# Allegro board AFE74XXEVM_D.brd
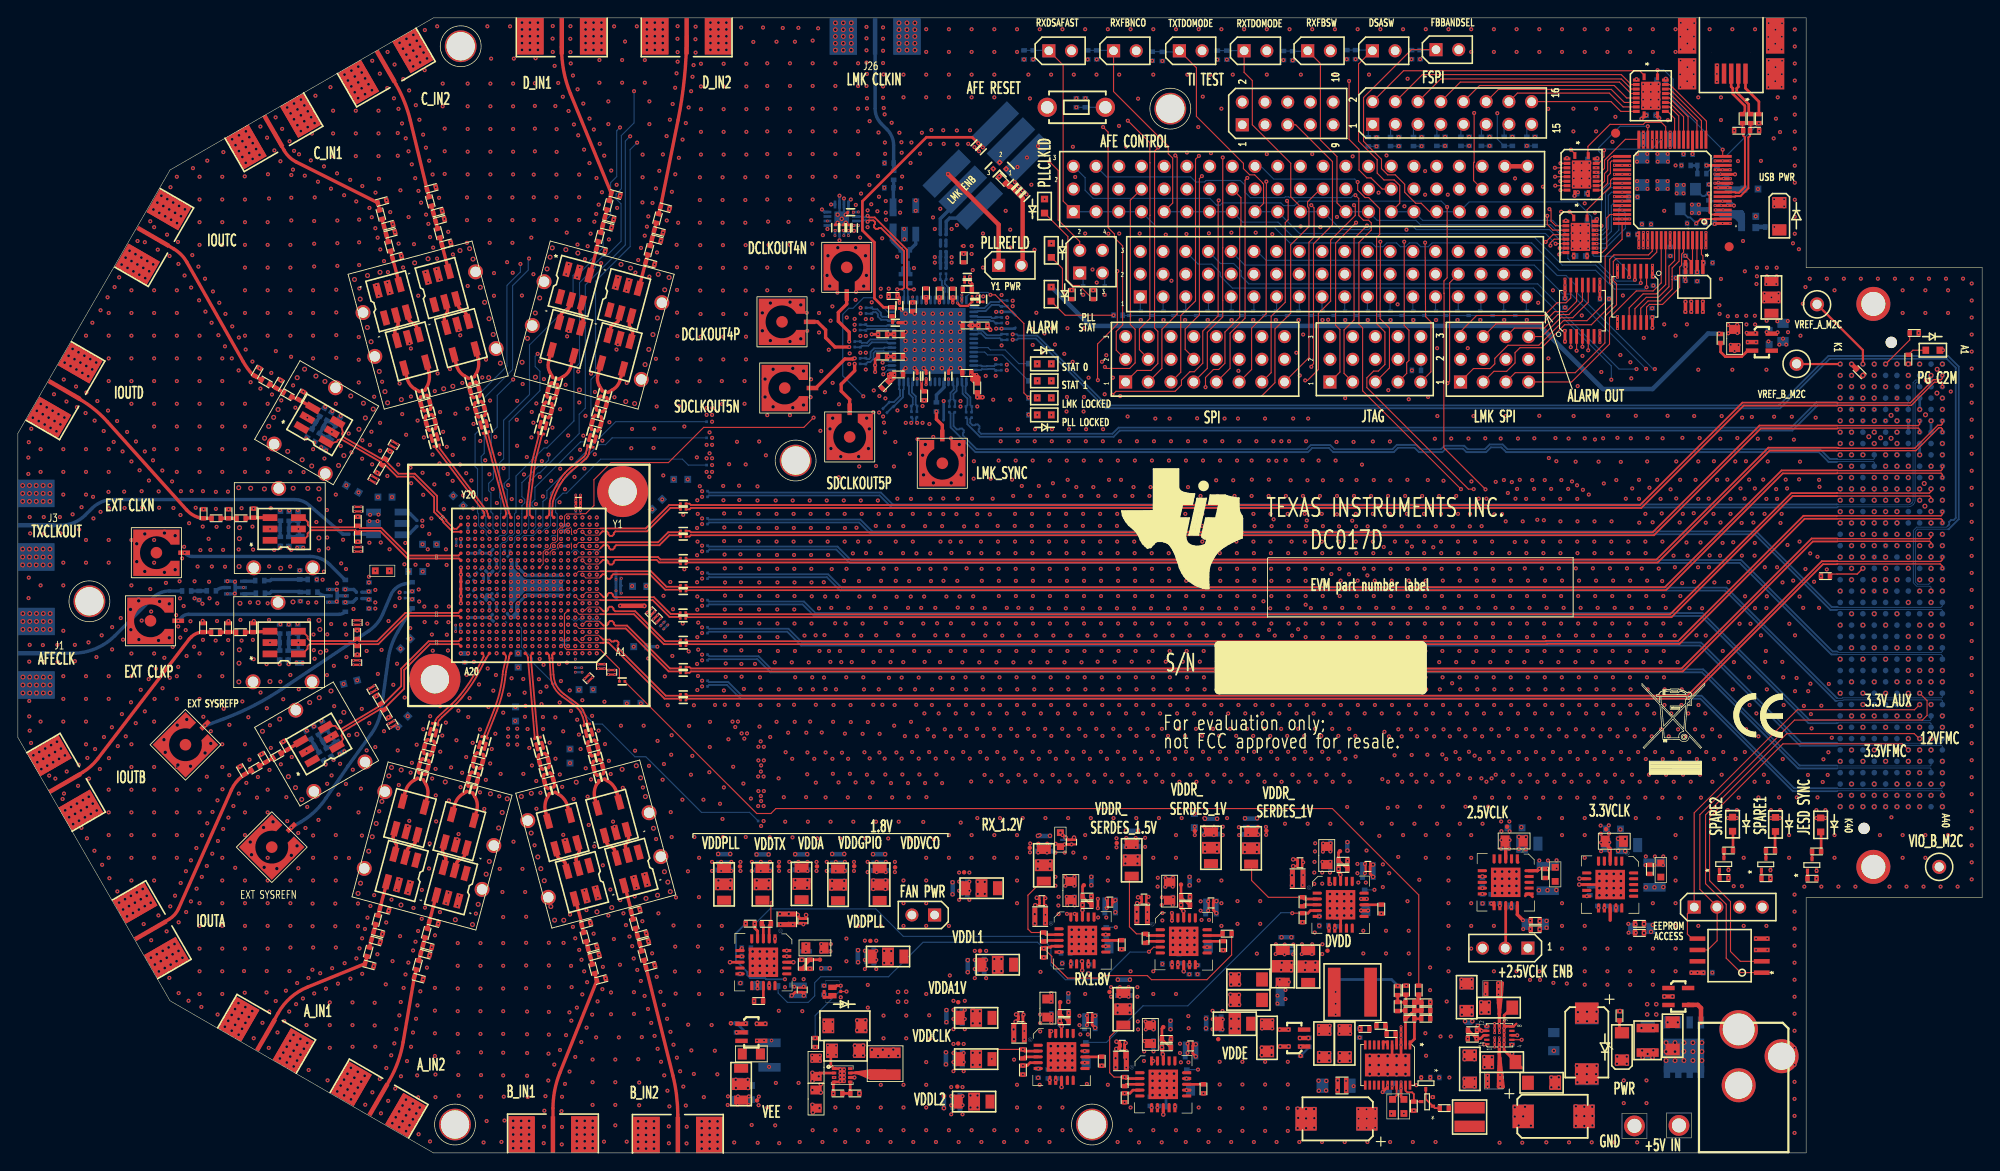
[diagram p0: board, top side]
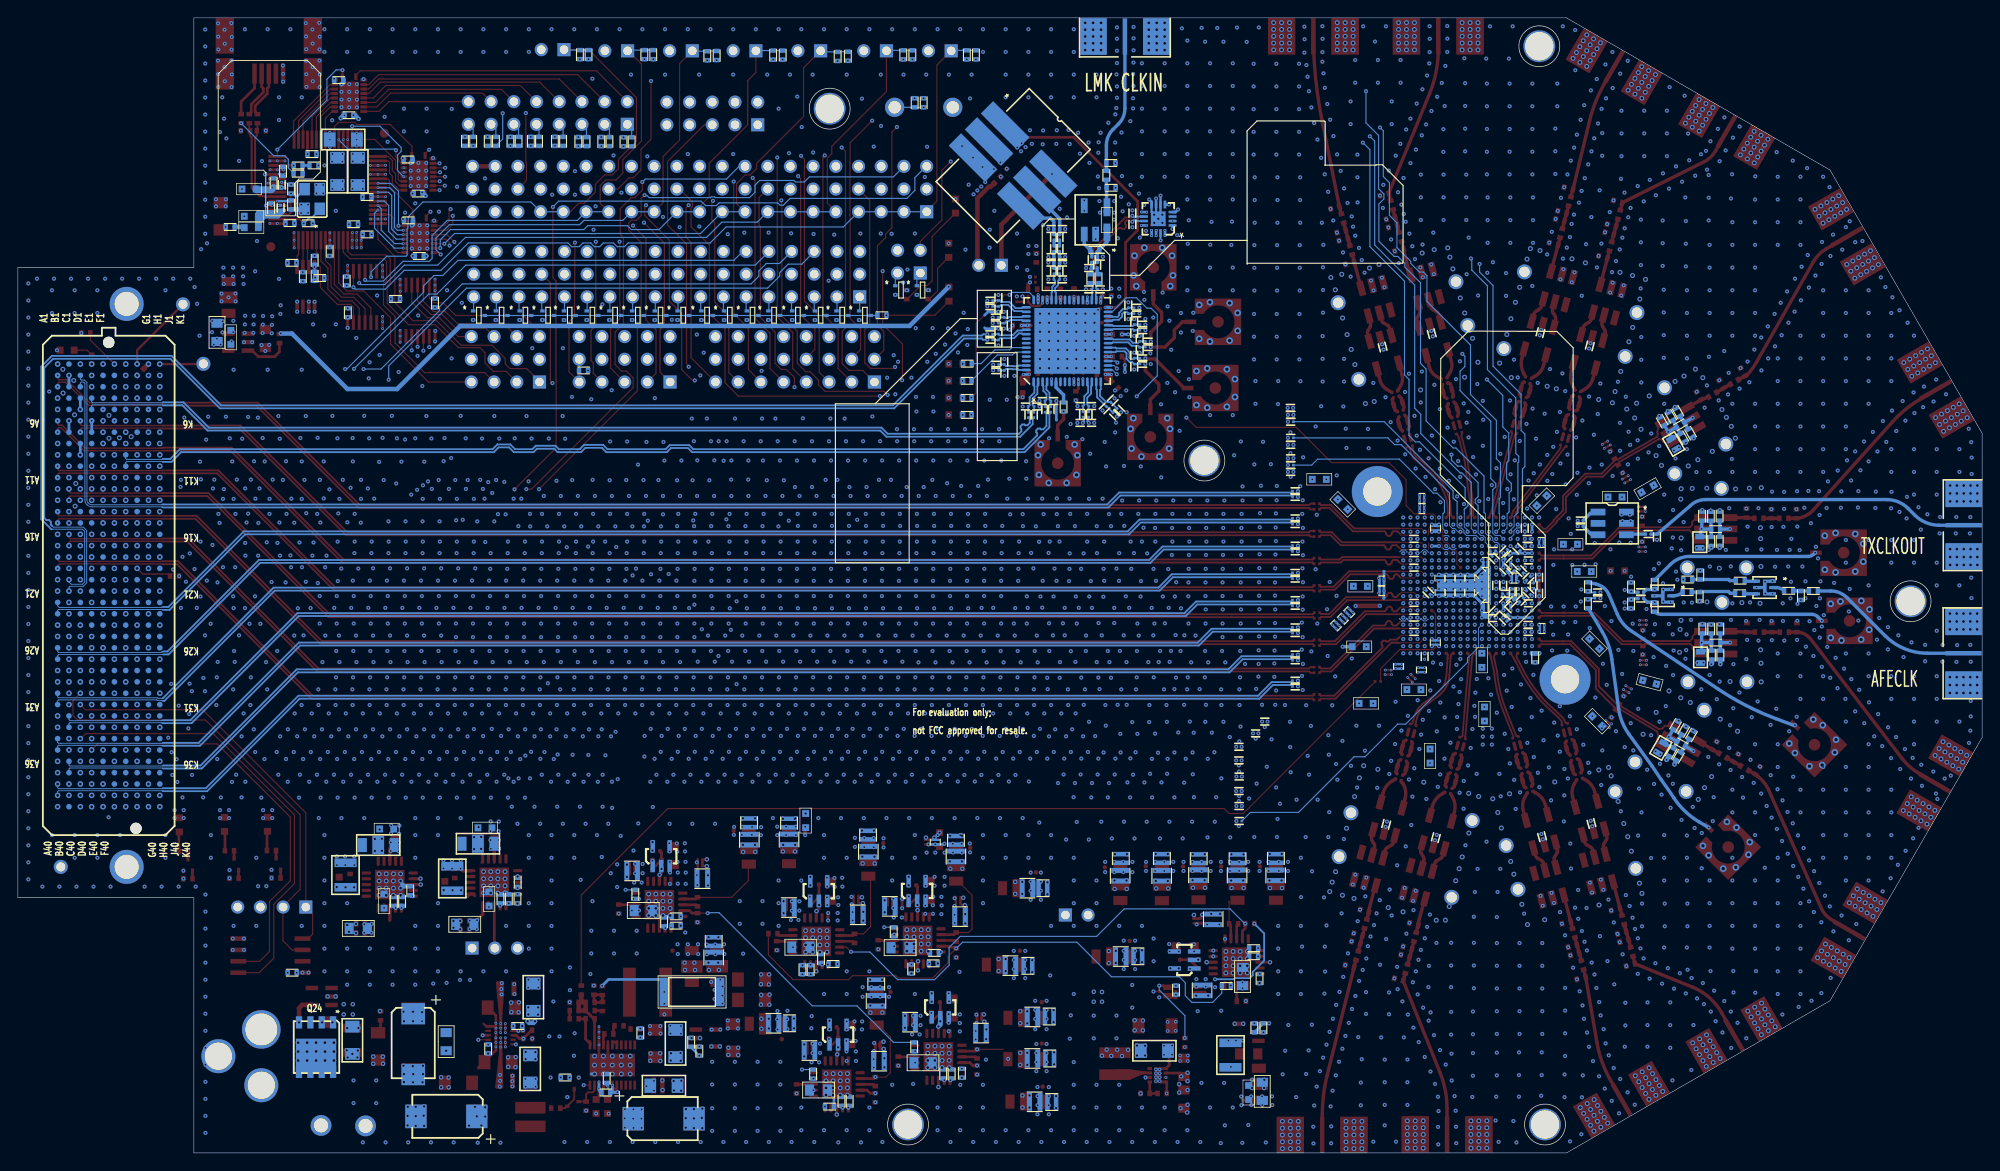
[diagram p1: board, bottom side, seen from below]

Outline 219.71 x 127 mm; copper layers: TOP, L2_GND, L3_PWR, L4_SIG, L5_GND, L6_SIG, L7_GND, L8_PWR_SIG, L9_GND, BOTTOM. Coordinates in mm from the lower left corner of the outline.
Outline path: 0,80.52 0,46.48 17.02,17.02 46.48,0 200.03,0 200.03,28.57 219.71,28.57 219.71,99.06 200.03,99.06 200.03,127 46.48,127 17.02,109.98 0,80.52

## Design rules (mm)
net group ADC_ALT_SYNC: nets ADC_ALT_SYNC_N ADC_ALT_SYNC_P
net group ADC_SYNC: nets ADC_SYNC_N ADC_SYNC_P
net group AIN1: nets AIN1M AIN1P
net group AIN2: nets AIN2M AIN2P
net group BIN1: nets BIN1M BIN1P
net group BIN2: nets BIN2M BIN2P
net group CAR_SYSREF: nets CAR_SYSREFM CAR_SYSREFP
net group CARSYSREF: nets CAR_SYSREF_M CAR_SYSREF_P
net group CIN1: nets CIN1M CIN1P
net group CIN2: nets CIN2M CIN2P
net group CLK: nets CLKN CLKP
net group CLK0_M2C: nets CLK0_M2C_N CLK0_M2C_P
net group CLK1_M2C: nets CLK1_M2C_N CLK1_M2C_P
net group CLK_LAO: nets CLK_LAO_0M CLK_LAO_0P
net group CLKIN1: nets CLKIN1_N CLKIN1_P
net group DAC_ALT_SYNC: nets DAC_ALT_SYNC_N DAC_ALT_SYNC_P
net group DAC_SYNC: nets DAC_SYNC_N DAC_SYNC_P
net group DCLKOUT4: nets DCLKOUT4N DCLKOUT4P
net group DCLKOUT6: nets DCLKOUT6N DCLKOUT6P
net group DCLKOUT10: nets DCLKOUT10N DCLKOUT10P
net group DIN1: nets DIN1M DIN1P
net group DIN2: nets DIN2M DIN2P
net group DP0_M2C: nets DP0_M2C_N DP0_M2C_P
net group DP1: nets DM DP
net group DP1_M2C: nets DP1_M2C_N DP1_M2C_P
net group DP2: nets CLKLA_0M CLKLA_0P
net group DP3: nets N19392142 N19392187
net group DP4: nets CLK_N CLK_P
net group DP5: nets FPGA_CLK1N FPGA_CLK1P
net group DP6: nets FPGA_CLK2N FPGA_CLK2P
net group DP7: nets OSCI OSCO
net group DP8: nets N19086842 N19086844
net group DP9: nets GTXCLKM GTXCLKP
net group DP10: nets GTX_CLKM GTX_CLKP
net group DP11: nets N18276385 N18284119
net group FPGA_CLK1: nets FPGA_CLK1_N FPGA_CLK1_P
net group FPGA_CLK2: nets FPGA_CLK2_N FPGA_CLK2_P
net group GBTCLK1_M2C: nets GBTCLK1_M2C_N GBTCLK1_M2C_P
net group LMK_CLKIN1: nets CLKIN1N CLKIN1P
net group OSCIN: nets OSCINN OSCINP
net group RX1: nets RX1N RX1P
net group RX2: nets RX2N RX2P
net group RX3: nets RX3N RX3P
net group RX4: nets RX4N RX4P
net group RX5: nets RX5N RX5P
net group RX6: nets RX6N RX6P
net group RX7: nets RX7N RX7P
net group RX8: nets RX8N RX8P
net group SDCLKOUT5: nets SDCLKOUT5N SDCLKOUT5P
net group SDCLKOUT7: nets SDCLKOUT7N SDCLKOUT7P
net group SYSR: nets SYSREF+ SYSREF-
net group SYSREF: nets SYSREFN SYSREFP
net group SYSREF-: nets SYSREF-N SYSREF-P
net group TX1: nets TX1N TX1P
net group TX2: nets TX2N TX2P
net group TX3: nets TX3N TX3P
net group TX4: nets TX4N TX4P
net group TX5: nets TX5N TX5P
net group TX6: nets TX6N TX6P
net group TX7: nets TX7N TX7P
net group TX8: nets TX8N TX8P
net group TXA: nets TXAM TXAP
net group TXB: nets TXBM TXBP
net group TXC: nets TXCM TXCP
net group TXD: nets TXDM TXDP
net group USB_D: nets USB_DM USB_DP
net group Y2: nets Y2_N Y2_P

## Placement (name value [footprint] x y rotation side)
C1  0.01uF  [0402]  32.92 64.16 0 bottom
C2  .1uF  [0201]  44.93 70.1 180 bottom
C3  .1uF  [0201]  37.34 69.24 180 bottom
C4  0.01uF  [0402]  18.87 62.88 0 bottom
C6  .1uF  [0201]  44.93 70.76 180 bottom
C7  0.01uF  [0402]  32.99 62.75 0 bottom
C9  .1uF  [0201]  76.84 52.83 180 bottom
C10  .1uF  [0201]  76.84 52.2 180 bottom
C11  .1uF  [0201]  76.84 55.12 180 bottom
C12  .1uF  [0201]  76.84 55.75 180 bottom
C13  .1uF  [0201]  74.42 50.67 180 top
C14  .1uF  [0201]  74.42 51.31 180 top
C15  .1uF  [0201]  74.42 53.72 180 top
C16  .1uF  [0201]  74.42 54.36 180 top
C17  .1uF  [0201]  76.84 58.8 180 bottom
C18  .1uF  [0201]  74.42 57.4 180 top
C19  .1uF  [0201]  76.84 58.17 180 bottom
C20  .1uF  [0201]  74.42 56.77 180 top
C21  .1uF  [0201]  76.84 61.85 180 bottom
C22  .1uF  [0201]  74.4 60.45 180 top
C23  .1uF  [0201]  76.84 61.21 180 bottom
C24  .1uF  [0201]  74.4 59.82 180 top
C25  .1uF  [0201]  76.84 64.9 180 bottom
C26  .1uF  [0201]  76.84 64.26 180 bottom
C27  .1uF  [0201]  74.42 62.86 180 top
C28  .1uF  [0201]  74.42 63.5 180 top
C29  .1uF  [0201]  76.84 67.94 180 bottom
C30  .1uF  [0201]  74.42 66.55 180 top
C31  .1uF  [0201]  76.84 67.31 180 bottom
C32  .1uF  [0201]  74.42 65.91 180 top
C33  .1uF  [0201]  76.84 70.36 180 bottom
C34  .1uF  [0201]  76.84 70.99 180 bottom
C35  .1uF  [0201]  74.42 68.96 180 top
C36  .1uF  [0201]  74.42 69.6 180 top
C37  .1uF  [0201]  76.84 73.41 180 bottom
C38  .1uF  [0201]  74.42 72.01 180 top
C39  .1uF  [0201]  76.84 74.04 180 bottom
C40  .1uF  [0201]  74.42 72.64 180 top
C41  .001uF  [0402]  118.39 117.5 90 bottom
C42  .001uF  [0402]  112.55 122.86 90 bottom
C43  .001uF  [0402]  134.16 122.83 90 bottom
C44  .001uF  [0402]  141.55 122.78 90 bottom
C45  .001uF  [0402]  148.64 122.89 90 bottom
C46  .001uF  [0402]  155.88 122.89 90 bottom
C47  .001uF  [0402]  119.66 122.86 90 bottom
C48  .001uF  [0402]  126.87 122.71 90 bottom
C49  0.1uF  [0201]  50.88 68.71 180 bottom
C50  10uF  [0603]  71.52 72.57 45 bottom
C51  1uF  [0204]  60.66 64.31 90 bottom
C52  .1uF  [0204]  59.51 64.31 90 bottom
C53  .1uF  [0204]  60.63 62.71 270 bottom
C54  .1uF  [0204]  57.3 64.31 90 bottom
C55  .1uF  [0204]  58.39 64.31 90 bottom
C56  .1uF  [0204]  59.51 62.71 270 bottom
C57  .1uF  [0204]  58.42 62.71 270 bottom
C58  .1uF  [0204]  57.33 62.71 270 bottom
C59  .1uF  [0204]  55.5 61.04 0 bottom
C60  .1uF  [0204]  55.55 66.07 0 bottom
C61  10uF  [0603]  49.25 72.97 135 bottom
C62  1uF  [0201]  51.89 67.61 225 bottom
C63  .1uF  [0204]  49.23 58.67 0 bottom
C64  .1uF  [0201]  50.77 67.89 180 bottom
C65  .1uF  [0201]  50.77 59.08 180 bottom
C66  10uF  [0603]  69.55 63.4 0 bottom
C67  1uF  [0204]  62.66 73.23 0 bottom
C68  .1uF  [0204]  61.14 69.9 90 bottom
C69  .1uF  [0204]  61.16 57.1 270 bottom
C70  .1uF  [0204]  62.66 72.09 0 bottom
C71  .1uF  [0204]  65.28 54.43 270 top
C72  .1uF  [0204]  62.71 54.04 270 bottom
C73  .1uF  [0204]  66.42 53.77 270 top
C74  .1uF  [0204]  65.28 54.43 270 bottom
C75  .1uF  [0204]  62.69 72.77 0 top
C76  10uF  [0603]  55.67 49.11 90 bottom
C77  1uF  [0201]  53.34 67.31 135 bottom
C78  10uF  [0603]  40.77 65.13 0 top
C79  1uF  [0201]  50.75 66.29 180 bottom
C80  .1uF  [0201]  50.75 61.49 180 bottom
C81  10uF  [0603]  116.61 35.05 90 top
C82  1uF  [0204]  71.5 59.77 315 top
C83  .1uF  [0204]  70.79 60.5 315 top
C84  .1uF  [0204]  67.16 63.98 0 bottom
C85  .1uF  [0204]  67.16 62.92 0 bottom
C86  .1uF  [0204]  70.79 60.5 315 bottom
C87  .1uF  [0204]  72.29 59.02 315 bottom
C88  .1uF  [0204]  117.09 34.77 90 bottom
C89  .1uF  [0204]  71.5 59.77 315 bottom
C90  .1uF  [0204]  117.86 34.77 90 top
C91  10uF  [0603]  44.5 65.05 180 bottom
C92  1uF  [0201]  50.75 62.69 225 bottom
C93  10uF  [0603]  43.05 48.31 225 bottom
C94  1uF  [0201]  50.75 64.29 135 bottom
C95  10uF  [0603]  46.05 68.1 180 bottom
C96  1uF  [0204]  52.35 64.31 0 bottom
C97  10uF  [0603]  43.36 56.97 225 bottom
C98  1uF  [0201]  52.48 62.79 270 bottom
C99  10uF  [0603]  63.56 51.83 0 bottom
C100  1uF  [0201]  53.34 62.56 180 bottom
C101  10uF  [0603]  41.06 73.38 180 bottom
C102  1uF  [0201]  51.54 65.1 225 bottom
C103  .1uF  [0201]  51.51 61.87 135 bottom
C104  10uF  [0603]  55.96 55.12 90 bottom
C105  1uF  [0201]  53.29 60.48 225 bottom
C106  .1uF  [0201]  53.14 66.67 135 bottom
C107  10uF  [0603]  61.76 44.41 270 bottom
C108  1uF  [0201]  52.55 65.35 225 bottom
C109  .1uF  [0201]  52.6 61.65 135 bottom
C110  1uF  [0402]  49.99 55.4 90 bottom
C111  10uF  [0603]  69.67 56.64 0 bottom
C112  1uF  [0201]  63.55 59.89 0 bottom
C113  .1uF  [0201]  63.55 67.11 0 bottom
C114  10uF  [0603]  74.14 75.36 180 bottom
C115  1uF  [0201]  63.55 68.71 0 bottom
C116  .1uF  [0201]  63.55 58.29 0 bottom
C117  10uF  [0603]  131.6 37.19 90 bottom
C118  1uF  [0201]  63.55 65.48 0 bottom
C119  .1uF  [0201]  63.55 61.54 0 bottom
C120  .1uF  [0204]  56.16 64.92 45 bottom
C121  .1uF  [0204]  56.18 62.1 315 bottom
C122  10uF  [0603]  68.9 50.3 0 bottom
C123  1uF  [0201]  54.74 67.36 0 bottom
C124  .1uF  [0204]  63.82 53.11 315 top
C125  .1uF  [0201]  62.36 55.55 90 bottom
C126  .1uF  [0201]  54.76 59.84 0 bottom
C127  0 ohm  [0201]  44.79 42.22 75 top
C129  0 ohm  [0201]  45.37 44.38 255 top
C130  0 ohm  [0201]  46.01 44.21 255 top
C131  3.9pF  [0201]  46.28 47.77 255 top
C132  0.01uF  [0402]  40.16 26.08 75 top
C133  0 ohm  [0201]  45.43 42.05 75 top
C135  0.1uF  [0201]  43.7 36.86 255 bottom
C136  3.9pF  [0201]  46.91 47.59 255 top
C137  0.01uF  [0402]  63.43 24.15 105 top
C139  0.1uF  [0201]  61.1 35.28 285 bottom
C140  0 ohm  [0201]  60.01 40.65 105 top
C141  0 ohm  [0201]  59.37 40.48 105 top
C142  0 ohm  [0201]  58.8 42.64 285 top
C143  0 ohm  [0201]  59.43 42.81 285 top
C144  3.9pF  [0201]  57.88 46.05 285 top
C145  3.9pF  [0201]  58.52 46.22 285 top
C146  3.9pF  [0201]  46.44 79.34 105 top
C147  3.9pF  [0201]  47.08 79.51 105 top
C148  0.01uF  [0402]  65.07 102.48 255 top
C149  0 ohm  [0201]  59.78 86.45 255 top
C150  0 ohm  [0201]  60.41 86.28 255 top
C151  0 ohm  [0201]  59.15 84.3 75 top
C152  0 ohm  [0201]  59.79 84.13 75 top
C153  3.9pF  [0201]  58.27 80.91 75 top
C154  3.9pF  [0201]  58.9 80.74 75 top
C155  0.01uF  [0402]  41.56 101.43 285 top
C156  0.1uF  [0201]  61.56 91.67 75 bottom
C157  0 ohm  [0201]  44.98 84.89 285 top
C158  0 ohm  [0201]  45.62 85.06 285 top
C159  0 ohm  [0201]  45.56 82.73 105 top
C160  0 ohm  [0201]  46.2 82.91 105 top
C161  0.1uF  [0201]  43.88 90.3 105 bottom
C183  .1uF  [0204]  41.88 47.96 300 top
C184  5600pF  [0402]  28.98 44.44 210 top
C185  .3pF  [0402]  29.94 45.58 300 top
C186  5600pF  [0402]  32.51 46.76 120 bottom
C187  1000pF  [0402]  33.66 45.77 210 bottom
C188  1000pF  [0402]  34.77 44.83 120 bottom
C189  1000pF  [0402]  33.96 44.37 120 bottom
C190  0.1uF  [0402]  34.29 47.83 120 bottom
C191  .1uF  [0402]  33.38 47.27 120 bottom
C192  0.1uF  [0603]  37.2 52.68 195 bottom
C193  0.1uF  [0402]  30.23 55.7 270 bottom
C194  .1uF  [0402]  31.29 58.62 90 bottom
C195  5600pF  [0402]  24.91 58.27 180 top
C196  .1uF  [0204]  37.95 59.34 90 top
C197  .3pF  [0402]  26.31 58.78 270 top
C198  5600pF  [0402]  29.29 58.62 270 bottom
C199  1000pF  [0402]  29.79 57.1 180 bottom
C200  1000pF  [0402]  30.3 58.62 270 bottom
C201  1000pF  [0402]  29.28 55.7 90 bottom
C202  5600pF  [0402]  30.15 84.84 150 top
C203  .1uF  [0204]  42.06 79.24 60 top
C204  .3pF  [0402]  31.67 84.72 240 top
C205  5600pF  [0402]  32.62 80.53 60 bottom
C206  1000pF  [0402]  33.75 81.47 150 bottom
C207  1000pF  [0402]  34.83 82.42 240 bottom
C208  1000pF  [0402]  34.03 82.88 240 bottom
C209  0.1uF  [0402]  35.8 81.86 60 bottom
C210  .1uF  [0402]  33.48 80.03 240 bottom
C211  0.1uF  [0603]  37.42 74.3 150 bottom
C212  0.1uF  [0402]  31.34 71.24 90 bottom
C213  .1uF  [0402]  30.35 71.23 90 bottom
C214  5600pF  [0402]  24.97 71.01 180 top
C215  .1uF  [0204]  38.04 72.03 90 top
C216  .3pF  [0402]  26.36 71.59 270 top
C217  5600pF  [0402]  29.37 71.25 270 bottom
C218  1000pF  [0402]  29.8 69.79 180 bottom
C219  1000pF  [0402]  30.3 68.42 90 bottom
C220  1000pF  [0402]  29.35 68.43 90 bottom
C221  0.1uF  [0201]  106.68 82.58 270 bottom
C222  .68uF  [0402]  97.77 94.11 270 top
C223  0.1uF  [0201]  107.21 112.75 225 top
C224  0.1uF  [0201]  106.07 82.58 270 bottom
C225  3900pF  [0201]  107.04 95.22 0 top
C226  47pF  [0201]  107.04 95.83 0 top
C227  0.1uF  [0201]  98.98 99.34 270 bottom
C228  0.1uF  [0201]  96.99 82.61 225 bottom
C229  0.1uF  [0201]  96.55 83.06 225 bottom
C230  0.1uF  [0201]  99.92 99.01 180 bottom
C231  0.1uF  [0201]  99.59 99.95 270 bottom
C233  .01uF  [0201]  91.41 103.53 90 top
C234  .01uF  [0201]  92.91 103.53 90 top
C235  .01uF  [0201]  92.3 103.53 90 top
C236  .01uF  [0201]  93.52 103.48 270 top
C237  .01uF  [0201]  93.14 105.26 180 top
C238  .01uF  [0201]  98.65 96.62 0 bottom
C239  .01uF  [0201]  99.92 96.62 180 bottom
C240  0.1uF  [0201]  110.36 93.47 0 bottom
C241  0.1uF  [0201]  110.36 92.86 0 bottom
C242  0.1uF  [0201]  111.31 108.34 225 top
C243  100pF  [0201]  111.74 107.9 225 top
C244  0.1uF  [0201]  103.2 101.17 270 bottom
C245  .1uF  [0201]  103.2 98.68 270 bottom
C246  2200pF  [0201]  112.17 107.47 225 top
C247  0.1uF  [0201]  102.87 97.74 0 bottom
C248  10pF  [0201]  112.6 107.04 225 top
C249  0.1uF  [0201]  110.97 95.35 0 bottom
C250  0.1uF  [0201]  110.97 94.74 0 bottom
C251  0.1uF  [0201]  103.81 101.17 270 bottom
C252  0.1uF  [0201]  103.81 98.68 270 bottom
C253  0.01uF  [0201]  93.29 90.17 180 bottom
C254  0.01uF  [0201]  93.29 90.78 180 bottom
C255  12pF  [0201]  104.14 97.74 180 bottom
C256  0.01uF  [0201]  93.9 88.29 180 bottom
C257  0.01uF  [0201]  93.9 88.9 180 bottom
C258  1uF  [0402]  100.11 94.67 90 top
C259  .1uF  [0201]  98.6 94.79 90 top
C260  0.01uF  [0201]  101.6 86.92 270 top
C261  1uF  [0402]  98.5 87.11 180 top
C262  1uF  [0402]  98.5 89.08 180 top
C263  1uF  [0402]  98.5 91.59 180 top
C264  1uF  [0402]  106.2 96.65 180 top
C265  .1uF  [0201]  106.2 98.02 180 top
C266  0.01uF  [0201]  106.2 97.41 180 top
C267  .1uF  [0201]  100.58 86.92 90 top
C268  10uF  [0402]  101.37 84.71 270 top
C269  1uF  [0402]  106.17 92.58 0 top
C270  1uF  [0402]  106.15 87.26 0 top
C271  .1uF  [0201]  190.2 108.31 90 bottom
C272  4.7uF  [0402]  191.11 108.53 90 bottom
C273  .1uF  [0402]  190.05 109.83 270 bottom
C274  .1uF  [0402]  186.82 111.76 0 bottom
C275  .1uF  [0402]  180.64 102.77 0 bottom
C276  .1uF  [0402]  182.17 103.91 180 bottom
C277  .1uF  [0402]  180.65 106.95 180 bottom
C278  10uF  [0805]  192.03 91.13 270 top
C279  .1uF  [0402]  189.28 104.04 180 bottom
C280  1.0uF  [0603]  195.89 91.25 270 bottom
C281  10uF  [0805]  197.44 91.81 270 bottom
C282  .1uF  [0201]  190.32 105.74 90 bottom
C283  4.7uF  [0402]  191.39 105.74 90 bottom
C284  .1uF  [0402]  184.84 100.86 90 bottom
C285  .1uF  [0402]  183.82 120.04 180 bottom
C286  .1uF  [0402]  182.68 116.1 180 bottom
C287  100uF  [1206]  183.31 113.39 0 bottom
C288  10uF  [1206]  183.98 109.82 90 bottom
C289  100uF  [1206]  181.69 109.82 90 bottom
C290  22pF  [0402]  192.48 114.38 180 top
C291  22pF  [0402]  194.26 114.38 0 top
C292  .1uF  [0402]  176.07 111.15 180 bottom
C293  .1uF  [0402]  174.93 107.34 180 bottom
C294  .1uF  [0402]  176.02 104.34 180 bottom
C295  .1uF  [0402]  174.8 100.36 180 bottom
C296  27pF  [0402]  187.22 104.01 180 bottom
C297  .1uF  [0402]  185.95 97.89 0 bottom
C298  27pF  [0402]  189.15 107.85 90 bottom
C299  .1uF  [0402]  182.93 97.56 90 bottom
C300  .1uF  [0402]  182.8 94.01 90 bottom
C301  47uF  [1210]  182.3 12.6 270 top
C302  22uF  [1206]  182.3 12.6 90 bottom
C303  100uF  [7343]  175.49 12.17 270 bottom
C304  22uF  [7343]  175.49 12.24 270 top
C305  10uF  [0805]  171.81 12.45 270 bottom
C306  10uF  [0805]  181.64 25.12 0 bottom
C307  .1uF  [0402]  181.38 24.61 180 top
C308  0.01uF  [0402]  181.38 25.63 180 top
C309  1.0uF  [0603]  183.77 31.65 270 top
C310  .1uF  [0402]  182.55 31.72 270 top
C311  47uF  [1210]  183.06 31.09 270 bottom
C312  10uF  [0805]  178.56 34.87 0 top
C313  1.0uF  [0603]  178.46 36.25 0 bottom
C314  1.0uF  [0603]  178.76 28.17 90 bottom
C315  10uF  [0805]  89.28 6.02 270 top
C316  1.0uF  [0603]  82.04 6.76 90 bottom
C317  10uF  [0805]  89.28 9.58 90 top
C318  10uF  [0805]  80.52 6.88 90 bottom
C321  47uF  [1210]  84.07 10.95 270 bottom
C322  22uF  [1206]  92.58 11.43 0 bottom
C323  22uF  [1206]  92.58 11.43 0 top
C325  10uF  [0508]  135.18 14.5 0 bottom
C326  1uF  [0306]  133.4 14.5 180 bottom
C327  .1uF  [0402]  152.46 14.22 0 top
C328  1.0uF  [0603]  155.03 5.2 270 top
C329  1000pF  [0402]  150.09 13.41 90 bottom
C330  100uF  [1206]  139.73 12.88 270 top
C331  10uF  [0508]  141.88 21.87 270 bottom
C332  1uF  [0306]  141.88 23.65 90 bottom
C333  22uF  [7343]  147.47 3.84 180 bottom
C334  100uF  [7343]  147.5 3.81 180 top
C335  22uF  [1206]  147.45 7.52 0 bottom
C336  1uF  [0306]  148.11 7.54 180 top
C337  100uF  [1206]  148.41 12.24 270 top
C338  680pF  [0402]  154.33 16.38 270 top
C340  100pF  [0402]  155.7 15.01 180 top
C341  4.7uF  [0603]  153.76 5.2 270 top
C342  2200pF  [0402]  157.48 15.01 0 top
C343  22uF  [1206]  165.99 10.16 0 top
C344  22uF  [1206]  165.63 16.26 0 top
C345  22uF  [1206]  162.41 9.4 270 top
C346  22uF  [1206]  162.41 9.4 270 bottom
C347  3300pF  [0402]  163.8 14.2 180 bottom
C348  10uF  [0508]  108.69 20.96 0 bottom
C349  1uF  [0306]  106.73 20.93 180 bottom
C350  10uF  [0508]  105.97 5.71 0 bottom
C351  1uF  [0306]  104.06 5.69 180 bottom
C352  10uF  [0508]  119.91 14.63 0 bottom
C353  .1uF  [0204]  112.17 15.24 180 top
C354  .1uF  [0204]  119.91 15.14 0 top
C355  10uF  [0508]  111.99 13.41 180 bottom
C356  10uF  [0508]  91.77 31.01 270 bottom
C357  1uF  [0306]  91.74 32.94 90 bottom
C358  0.01uF  [0402]  112.42 11.07 90 top
C359  10uF  [0508]  106.22 10.57 0 bottom
C360  1uF  [0306]  104.29 10.57 180 bottom
C361  1uF  [0402]  121.23 10.26 270 top
C362  10uF  [0805]  118.47 10.08 180 bottom
C363  10uF  [0508]  96.42 31.01 270 bottom
C364  1uF  [0306]  96.34 32.94 90 bottom
C365  10uF  [0508]  106.22 15.21 0 bottom
C366  1uF  [0306]  104.34 15.27 180 bottom
C367  10uF  [0508]  79.02 31.06 270 bottom
C368  1uF  [0306]  78.99 32.94 90 bottom
C369  10uF  [0508]  96.34 21.97 0 bottom
C370  1uF  [0306]  94.44 22 180 bottom
C371  10uF  [0508]  87.25 18.19 270 bottom
C372  .1uF  [0204]  87.73 18.24 270 top
C373  .1uF  [0204]  87.81 25.96 90 top
C374  10uF  [0508]  86 26.14 90 bottom
C375  1uF  [0306]  83.29 32.92 90 bottom
C376  10uF  [0508]  106.78 29.62 0 bottom
C377  0.01uF  [0402]  83.72 25.63 0 top
C378  10uF  [0508]  83.34 31.06 270 bottom
C379  1uF  [0306]  105.05 29.62 180 bottom
C380  10uF  [0805]  82.73 19.74 90 bottom
C381  1uF  [0402]  82.85 16.99 180 top
C382  10uF  [0508]  87.66 31.09 270 bottom
C383  1uF  [0306]  87.63 32.92 90 bottom
C384  10uF  [0508]  122.17 27.58 0 bottom
C385  .1uF  [0204]  122.15 28.07 0 top
C386  .1uF  [0204]  114.53 28.22 180 top
C387  10uF  [0508]  114.33 26.44 180 bottom
C388  1uF  [0306]  114.78 34.98 90 bottom
C389  10uF  [0508]  114.78 33.17 270 bottom
C390  0.01uF  [0402]  114.76 24.16 90 top
C391  10uF  [0805]  121.03 22.96 180 bottom
C392  1uF  [0402]  123.47 23.29 270 top
C393  10uF  [0508]  131.17 11.46 0 bottom
C394  10uF  [0508]  123.72 17.02 270 bottom
C395  1uF  [0306]  123.7 18.9 90 bottom
C396  .1uF  [0204]  131.17 11.96 0 top
C397  .1uF  [0204]  123.55 12.04 180 top
C398  10uF  [0508]  123.39 10.26 180 bottom
C399  0.01uF  [0402]  123.8 7.98 90 top
C400  1uF  [0402]  132.61 7.16 270 top
C401  10uF  [0805]  130.15 7.04 180 bottom
C402  10uF  [0508]  133.45 35.08 270 bottom
C403  1uF  [0306]  133.45 36.91 90 bottom
C404  10uF  [0508]  151 31.55 0 bottom
C405  .1uF  [0204]  151 32.05 0 top
C406  .1uF  [0204]  143.41 32.46 180 top
C407  10uF  [0508]  143.15 30.68 180 top
C408  0.01uF  [0402]  143.69 28.09 90 top
C409  1uF  [0402]  152.5 27.28 270 top
C410  10uF  [0508]  137.9 35.05 270 bottom
C411  1uF  [0306]  137.92 36.93 90 bottom
C412  10uF  [0805]  149.76 27.13 180 bottom
C413  10uF  [0508]  133.45 27.46 0 bottom
C414  .1uF  [0204]  133.45 27.97 0 top
C415  .1uF  [0204]  125.96 28.4 180 top
C416  1uF  [0306]  124.61 35.56 90 bottom
C417  10uF  [0508]  124.59 33.71 270 bottom
C418  10uF  [0508]  125.76 26.64 180 bottom
C419  0.01uF  [0402]  126.14 24 90 top
C420  10uF  [0805]  132.13 23.01 180 bottom
C421  1uF  [0402]  134.82 23.19 270 top
C422  1uF  [0402]  189.03 20.17 180 bottom
C423  0.1uF  [0201]  93.9 92.06 180 bottom
C424  0.1uF  [0201]  93.9 92.67 180 bottom
C425  0.1uF  [0201]  94.56 93.93 180 bottom
C426  0.1uF  [0201]  94.56 94.56 180 bottom
C427  0.1uF  [0201]  110.97 91.59 0 bottom
C428  0.1uF  [0201]  110.97 90.98 0 bottom
C429  .1uF  [0201]  53.39 59.72 225 bottom
C430  .1uF  [0201]  50.77 58.29 180 bottom
C431  .1uF  [0201]  51.87 62.79 270 bottom
C432  1.0uF  [0603]  167 28.42 90 bottom
C433  10uF  [0805]  167.36 34.9 0 top
C434  1.0uF  [0603]  167.46 36.37 0 bottom
C435  47uF  [1210]  171.12 30.71 270 bottom
C436  1.0uF  [0603]  171.96 31.17 270 top
C437  .1uF  [0402]  170.84 31.27 270 top
C438  .1uF  [0402]  169.72 25.02 180 top
C439  0.01uF  [0402]  169.72 25.96 180 top
C440  10uF  [0805]  169.72 25.58 0 bottom
C441  .1uF  [0204]  39.67 51.87 120 top
C442  .1uF  [0204]  37.9 54.86 270 top
C443  .1uF  [0402]  173.05 95.1 270 bottom
C444  .1uF  [0402]  177.47 95.55 180 bottom
C445  22uF  [1206]  162.05 17.42 90 top
C446  22uF  [1206]  162.05 17.42 90 bottom
C447  100uF  [1206]  146.15 12.24 270 bottom
C448  100uF  [1206]  146.1 12.24 270 top
C449  100uF  [1206]  137.64 17.12 180 top
C450  100uF  [1206]  137.64 19.41 180 top
C451  10uF  [0508]  111.99 13.39 180 top
C452  10uF  [0508]  86 26.14 90 top
C453  10uF  [0508]  114.35 26.44 180 top
C454  10uF  [0508]  123.39 10.29 180 top
C455  10uF  [0508]  143.15 30.68 180 bottom
C456  10uF  [0508]  125.76 26.64 180 top
C457  .1uF  [0204]  39.79 75.36 240 top
C458  .1uF  [0204]  38.02 67.54 270 top
C459  .1uF  [0201]  54.58 66.52 45 bottom
C460  .1uF  [0201]  54.53 60.58 315 bottom
C461  .1uF  [0201]  49.56 62.61 270 bottom
C462  1uF  [0201]  49.56 64.39 90 bottom
C463  .1uF  [0204]  49.3 68.3 0 bottom
C464  .1uF  [0201]  53.34 65.33 225 bottom
C465  1uF  [0201]  53.39 61.67 135 bottom
C466  22uF  [7343]  171.78 4.09 0 top
C467  100uF  [7343]  171.78 4.09 0 bottom
C468  22uF  [1206]  170.43 7.85 180 top
C469  0 ohm  [0201]  50.31 40.74 75 top
C470  0 ohm  [0201]  50.95 40.57 75 top
C471  0.01uF  [0402]  45.68 24.6 75 top
C472  0 ohm  [0201]  50.89 42.9 255 top
C473  0 ohm  [0201]  51.53 42.73 255 top
C474  3.9pF  [0201]  51.8 46.29 255 top
C475  3.9pF  [0201]  52.43 46.12 255 top
C476  0.1uF  [0201]  49.22 35.39 255 bottom
C477  0 ohm  [0201]  64.89 41.96 105 top
C478  0 ohm  [0201]  65.53 42.13 105 top
C479  0.01uF  [0402]  68.95 25.63 105 top
C480  0 ohm  [0201]  64.32 44.12 285 top
C481  0 ohm  [0201]  64.95 44.29 285 top
C482  3.9pF  [0201]  63.4 47.53 285 top
C483  3.9pF  [0201]  64.04 47.7 285 top
C484  0.1uF  [0201]  66.66 36.77 285 bottom
C485  0 ohm  [0201]  50.5 86.37 285 top
C486  0 ohm  [0201]  51.14 86.54 285 top
C487  0.01uF  [0402]  47.08 102.91 285 top
C488  0 ohm  [0201]  51.08 84.21 105 top
C489  0 ohm  [0201]  51.72 84.38 105 top
C490  3.9pF  [0201]  51.96 80.82 105 top
C491  3.9pF  [0201]  52.6 80.99 105 top
C492  0.1uF  [0201]  49.4 91.78 105 bottom
C493  0 ohm  [0201]  65.3 84.97 255 top
C494  0 ohm  [0201]  65.94 84.8 255 top
C495  0.01uF  [0402]  70.59 101 255 top
C496  0 ohm  [0201]  64.67 82.82 75 top
C497  0 ohm  [0201]  65.31 82.65 75 top
C498  3.9pF  [0201]  64.42 79.26 75 top
C499  3.9pF  [0201]  63.79 79.43 75 top
C500  0.1uF  [0201]  67.06 90.17 75 bottom
C501  3300pF  [0402]  156.15 5.24 270 top
D1  LED AMBER  [LED_0603]  115.6 100.99 270 top
D2  LED AMBER  [LED_0603]  114.83 105.94 270 top
D3  LED AMBER  [LED_0603]  115.57 96.09 270 top
D4  LED GREEN  [LED_0603]  114.81 88.29 0 top
D5  LED GREEN  [LED_0603]  114.81 86.39 0 top
D6  LED GREEN  [LED_0603]  114.81 82.58 0 top
D7  LED GREEN  [LED_0603]  114.81 84.48 0 top
D8  LED GREEN  [LED_0603]  201.65 36.7 270 top
D9  LED GREEN  [LED_0603]  196.6 36.75 270 top
D10  LED GREEN  [LED_0603]  191.8 36.78 270 top
D11  LED AMBER  [LED_1206]  197.03 104.8 90 top
D12  LED GREEN  [LED_1206]  179.43 11.91 270 top
D13  MBRA120  [DIODE_SM_DO_214AC]  92.51 14.22 180 top
D14  LED GREEN  [LED_0603]  214.2 89.81 0 top
F1  FUSE 7.0A 24V FAST  [1206]  185.09 13.11 90 top
FB1  120  [0402]  110.12 108.87 135 top
FB2  120  [0402]  97.89 95.88 0 top
FB3  120  [0402]  96.72 89.1 0 top
FB4  120  [0402]  96.72 91.59 0 top
FB5  120  [0402]  97.01 85.93 45 top
FB6  120  [0402]  105.79 100.15 270 top
FB7  120  [0402]  101.57 96.22 270 top
FB8  120  [0402]  103.1 96.19 270 top
FB9  120  [0402]  104.57 96.19 270 top
FB10  120  [0402]  107.95 92.58 180 top
FB11  120  [0402]  107.31 85.6 90 top
FB12  60 OHM @ 100MHz  [0603]  193.85 107.85 180 bottom
FB13  27uF  [1206_BEAD_NFM31P]  196.14 95.72 90 top
FB14  60 OHM @ 100MHz  [0603]  193.6 104.8 180 bottom
FB15  60 OHM @ 100MHz  [0603]  193.6 103.53 180 bottom
FB17  27uF  [1206_BEAD_NFM31P]  179.4 34.44 180 bottom
FB18  27uF  [1206_BEAD_NFM31P]  80.9 7.7 270 top
FB19  YFF31HC1H153MT00  [FILTER_3_SM_YFF31HC]  136.12 14.45 180 top
FB20  YFF31HC1H153MT00  [FILTER_3_SM_YFF31HC]  141.48 20.88 90 top
FB21  27uF  [1206_BEAD_NFM31P]  109.6 21.06 180 top
FB22  27uF  [1206_BEAD_NFM31P]  106.96 5.74 180 top
FB23  27uF  [1206_BEAD_NFM31P]  91.74 30 90 top
FB24  27uF  [1206_BEAD_NFM31P]  107.19 10.49 180 top
FB25  27uF  [1206_BEAD_NFM31P]  96.39 30.02 90 top
FB26  27uF  [1206_BEAD_NFM31P]  107.19 15.11 180 top
FB27  27uF  [1206_BEAD_NFM31P]  78.99 30.05 90 top
FB28  27uF  [1206_BEAD_NFM31P]  97.33 21.97 180 top
FB29  27uF  [1206_BEAD_NFM31P]  83.29 30.05 270 top
FB30  27uF  [1206_BEAD_NFM31P]  107.8 29.62 180 top
FB31  27uF  [1206_BEAD_NFM31P]  87.66 30.1 90 top
FB32  27uF  [1206_BEAD_NFM31P]  114.76 32.18 90 top
FB33  27uF  [1206_BEAD_NFM31P]  123.65 16.08 90 top
FB34  27uF  [1206_BEAD_NFM31P]  133.45 34.14 90 top
FB35  27uF  [1206_BEAD_NFM31P]  137.95 34.09 90 top
FB36  27uF  [1206_BEAD_NFM31P]  124.59 32.74 90 top
FB37  27uF  [1206_BEAD_NFM31P]  168.25 34.59 180 bottom
FB38  YFF31HC1H153MT00  [FILTER_3_SM_YFF31HC]  144.32 20.85 90 top
HS1  HEAT SINK  [HEATSINK_27X27MM_ATS]  57.15 63.5 0 top
J1  SMA END LAUNCH  [SMA_SMEL_DUAL_PSF-S01_250X215]  0.05 55.91 270 bottom
J2  SMP CONN  [SMP_B120]  14.83 59.54 90 top
J3  SMA END LAUNCH  [SMA_SMEL_DUAL_PSF-S01_250X215]  0.03 70.23 270 bottom
J4  SMP CONN  [SMP_B120]  15.49 67.16 90 top
J5  SMP CONN  [SMP_B120]  28.4 34.21 135 top
J6  SMP CONN  [SMP_B120]  18.75 45.67 135 top
J7  HTSW-118-07-G-T  [HDR_THVT_3X18_100_M]  147.14 98.32 90 top
J8  HMTSW-102-07-G-D-.240  [HDR_THVT_2X2_100_M]  118.77 98.45 90 top
J9  HTSW-121-07-G-T  [HDR_THVT_3X21_100_M]  143.46 107.85 90 top
J10  HTSW-105-07-G-T-.240  [HDR_THVT_3X5_100_M]  146.76 86.26 90 top
J11  HMTSW-105-07-G-D-.240  [HDR_THVT_2X5_100_M]  136.96 115.04 90 top
J12  HMTSW-108-07-G-D-.240  [HDR_THVT_2X8_100_M]  151.54 115.09 90 top
J13  HTSW-108-07-G-T-.240  [HDR_THVT_3X8_100_M]  123.9 86.26 90 top
J14  SMA, JACK, END LAUNCH  [SMA_SMEL_DUAL_PSF-S01_250X215]  26.75 11.46 150 top
J15  SMA, JACK, END LAUNCH  [SMA_SMEL_DUAL_PSF-S01_250X215]  39.32 4.22 150 top
J16  SMA, JACK, END LAUNCH  [SMA_SMEL_DUAL_PSF-S01_250X215]  59.85 0.03 180 top
J17  SMA, JACK, END LAUNCH  [SMA_SMEL_DUAL_PSF-S01_250X215]  73.82 -0.03 180 top
J18  SMA, JACK, END LAUNCH  [SMA_SMEL_DUAL_PSF-S01_250X215]  27.56 116.08 30 top
J19  SMA, JACK, END LAUNCH  [SMA_SMEL_DUAL_PSF-S01_250X215]  40.13 123.32 30 top
J20  SMA, JACK, END LAUNCH  [SMA_SMEL_DUAL_PSF-S01_250X215]  60.83 126.97 0 top
J21  SMA, JACK, END LAUNCH  [SMA_SMEL_DUAL_PSF-S01_250X215]  74.8 126.97 0 top
J22  SMA END LAUNCH  [SMA_SMEL_DUAL_PSF-S01_250X215]  13.11 23.9 120 top
J23  SMA END LAUNCH  [SMA_SMEL_DUAL_PSF-S01_250X215]  3.52 40.38 120 top
J24  SMA END LAUNCH  [SMA_SMEL_DUAL_PSF-S01_250X215]  13.39 103.5 60 top
J25  SMA END LAUNCH  [SMA_SMEL_DUAL_PSF-S01_250X215]  3.46 86.37 60 top
J26  SMA, JACK, END LAUNCH  [SMA_SMEL_DUAL_PSF-S01_250X215]  95.89 126.95 180 bottom
J27  SMP CONN  [SMP_B120]  85.47 92.99 90 top
J28  SMP CONN  [SMP_B120]  92.71 99.09 0 top
J29  SMP CONN  [SMP_B120]  93.04 80.11 180 top
J30  SMP CONN  [SMP_B120]  85.78 85.58 90 top
J31  SMP CONN  [SMP_B120]  103.4 77.17 180 top
J32  CON_SMVT_40x10_SEAM  [CON_SMVT_40X10_SEAM_MTG]  209.55 63.5 90 bottom
J33  USB_MINI_AB  [CON_SMRT_USBMINI_AB_F_MOD]  191.64 124.49 270 top
J35  CONN JACK PWR  [CON_RAPC722_JACK_THVT_3]  192.48 10.69 0 top
J36  HTSW-104-07-G-T-.240  [HDR_THVT_3X4_100_M]  161.37 86.26 90 top
J37  HDR, THVT, 4POS, .100, GOLD  [HDR_THVT_1X4_100_M]  187.5 27.51 90 top
J38  HEADER 2POS, FAN POWER  [HDR_THVT_1X2_100_M]  102.54 26.62 270 top
JP1  HEADER_1x2_100_430L  [HDR_THVT_1X2_100_M]  109.7 99.31 90 top
JP2  HEADER_1x2_100_430L  [HDR_THVT_1X2_100_M]  115.32 123.32 90 top
JP3  HEADER_1x2_100_430L  [HDR_THVT_1X2_100_M]  122.56 123.32 90 top
JP4  HEADER_1x2_100_430L  [HDR_THVT_1X2_100_M]  129.92 123.32 90 top
JP5  HEADER_1x2_100_430L  [HDR_THVT_1X2_100_M]  137.16 123.32 90 top
JP6  HEADER_1x2_100_430L  [HDR_THVT_1X2_100_M]  144.27 123.32 90 top
JP7  HEADER_1x2_100_430L  [HDR_THVT_1X2_100_M]  151.51 123.32 90 top
JP8  HEADER_1x2_100_430L  [HDR_THVT_1X2_100_M]  158.62 123.44 90 top
JP9  JUMPER_1x3  [HDR_THVT_1X3_100_M]  168.9 22.92 270 top
L1  20nH  [0402]  39.27 61.42 270 bottom
L2  20nH  [0402]  39.27 63.32 90 bottom
L3  3.3nH  [0402]  45.38 43.22 165 top
L4  15nH  [0402]  64.27 22.96 195 top
L5  10nH  [0402]  45.98 45.38 165 top
L6  15nH  [0402]  40.29 24.62 165 top
L7  15nH  [0402]  41 27.25 165 top
L8  15nH  [0402]  63.56 25.61 195 top
L9  3.3nH  [0402]  59.4 41.65 195 top
L10  10nH  [0402]  58.84 43.81 195 top
L11  15nH  [0402]  41.69 102.89 195 top
L12  15nH  [0402]  42.4 100.24 195 top
L13  3.3nH  [0402]  45.57 83.89 195 top
L14  10nH  [0402]  46.18 81.74 195 top
L15  15nH  [0402]  65.91 103.68 165 top
L16  15nH  [0402]  65.2 101.03 165 top
L17  3.3nH  [0402]  59.8 85.28 165 top
L18  10nH  [0402]  59.2 83.13 165 top
L27  560nH  [0402]  40.34 50.7 120 top
L28  560nH  [0402]  41.22 49.15 120 top
L29  120nH @ 7.9MHz  [IND_0603]  35.94 45.31 120 bottom
L31  120nH @ 7.9MHz  [IND_0603]  31.5 55.45 90 bottom
L33  560nH  [0402]  37.95 58.01 90 top
L34  560nH  [0402]  37.95 56.21 90 top
L35  560nH  [0402]  41.36 78.09 60 top
L36  560nH  [0402]  40.46 76.53 60 top
L37  120nH @ 7.9MHz  [IND_0603]  34.5 79.32 60 bottom
L39  120nH @ 7.9MHz  [IND_0603]  31.58 68.33 90 bottom
L41  560nH  [0402]  38.03 70.68 90 top
L42  560nH  [0402]  38.03 68.89 90 top
L43  11nH  [0402]  99.75 97.82 90 bottom
L44  11nH  [0402]  98.83 97.82 90 bottom
L45  2.2uH  [IND_SM_XFL4015]  97 9.98 90 top
L46  330nH  [IND_SM_XAL60XX]  149.28 17.98 180 top
L47  470nH  [IND_0806]  165.07 8.05 180 top
L48  470nH  [IND_0806]  164.92 18.36 180 top
L49  1.5uH  [IND_SM_3020]  162.38 4.01 270 top
L50  15nH  [0402]  45.81 23.15 165 top
L51  15nH  [0402]  46.52 25.77 165 top
L52  3.3nH  [0402]  50.9 41.75 165 top
L53  10nH  [0402]  51.5 43.9 165 top
L54  15nH  [0402]  69.79 24.44 195 top
L55  15nH  [0402]  69.08 27.09 195 top
L56  3.3nH  [0402]  64.92 43.13 195 top
L57  10nH  [0402]  64.36 45.29 195 top
L58  15nH  [0402]  47.21 104.37 195 top
L59  15nH  [0402]  47.92 101.72 195 top
L60  3.3nH  [0402]  51.09 85.37 195 top
L61  10nH  [0402]  51.7 83.22 195 top
L62  15nH  [0402]  71.43 102.2 165 top
L63  15nH  [0402]  70.72 99.55 165 top
L64  3.3nH  [0402]  65.32 83.8 165 top
L65  10nH  [0402]  64.72 81.65 165 top
MT1  STANDOFF,  4-40, 3/16 Rd x 1 3/16 Length, ALUM  [MFG125_PLATED]  128.91 116.84 0 top
MT2  STANDOFF,  4-40, 3/16 Rd x 1 3/16 Length, ALUM  [MFG125_PLATED]  8 61.72 0 top
MT3  STANDOFF,  4-40, 3/16 Rd x 1 3/16 Length, ALUM  [MFG125_PLATED]  48.9 3.17 0 top
MT4  STANDOFF,  4-40, 3/16 Rd x 1 3/16 Length, ALUM  [MFG125_PLATED]  49.53 123.83 0 top
MT5  STANDOFF,  4-40, 3/16 Rd x 1 3/16 Length, ALUM  [MFG125_PLATED]  120.14 3.17 0 top
MT6  STANDOFF,  4-40, 3/16 Rd x 1 3/16 Length, ALUM  [MFG125_PLATED]  87 77.47 0 top
NOREF  -  []  70.6 38.06 0 top
NOREF#2  -  []  39.92 89.12 0 top
NOREF#3  -  []  46.48 127 0 top
NOREF#4  -  []  51.92 29.49 0 top
NOREF#5  -  []  28.33 47.64 0 top
NOREF#6  -  []  200.03 99.06 90 top
NOREF#7  -  []  41.04 40.42 0 top
NOREF#8  -  []  0 80.52 90 top
NOREF#9  -  []  -113.79 -136.65 0 top
NOREF#10  -  []  96.52 17.14 0 top
NOREF#11  -  []  0 46.48 90 top
NOREF#12  -  []  50.51 40.63 0 top
NOREF#13  -  []  38.74 31.83 0 top
NOREF#14  -  []  17.02 109.98 0 top
NOREF#15  -  []  59.91 101.41 0 top
NOREF#16  -  []  21.59 204.6 90 top
NOREF#17  -  []  50.87 25.56 0 top
NOREF#18  -  []  37.56 83.73 0 top
NOREF#19  -  []  50.67 25.4 90 top
NOREF#20  -  []  78 42.52 0 top
NOREF#21  -  []  41.28 46.1 0 top
NOREF#22  -  []  59.33 28.6 0 top
NOREF#23  -  []  38.61 94.03 0 top
NOREF#24  -  []  128.02 47.37 0 top
NOREF#25  -  []  45.15 58 0 top
NOREF#26  -  []  46.48 0 0 top
NOREF#27  -  []  24.78 61.6 0 top
NOREF#28  -  []  57.03 37.19 0 top
NOREF#29  -  []  21.59 201.17 90 top
NOREF#30  -  []  53.49 90 0 top
NOREF#31  -  []  37.56 97.95 0 top
NOREF#32  -  []  57.54 92.57 0 top
NOREF#33  -  []  188.7 59.36 0 top
NOREF#34  -  []  30.8 88.04 0 top
NOREF#35  -  []  17.02 17.02 90 top
NOREF#36  -  []  219.71 28.57 90 top
NOREF#37  -  []  487.17 174.75 0 top
NOREF#38  -  []  105.41 36.83 0 top
NOREF#39  -  []  96.52 18.41 0 top
NOREF#40  -  []  200.03 28.57 0 top
NOREF#41  -  []  46.48 0 90 top
NOREF#42  -  []  45.72 16.51 0 top
NOREF#43  -  []  66.44 102.22 0 top
NOREF#44  -  []  105.41 39.37 0 top
NOREF#45  -  []  57.54 37.48 0 top
NOREF#46  -  []  12.7 205.74 90 top
NOREF#47  -  []  234.85 24 0 top
NOREF#48  -  []  24.85 74.36 0 top
NOREF#49  -  []  65.48 13.64 90 top
NOREF#50  -  []  53.34 16.51 90 top
NOREF#51  -  []  59.91 87.18 0 top
NOREF#52  -  []  28.33 47.64 0 top
NOREF#53  -  []  50.87 11.34 0 top
NOREF#54  -  []  51.92 98.5 0 top
NOREF#55  -  []  49.58 18.16 0 top
NOREF#56  -  []  54 90.29 0 top
NOREF#57  -  []  50.87 25.56 0 top
NOREF#58  -  []  37.56 97.95 0 top
NOREF#59  -  []  43.38 11.94 90 top
NOREF#60  -  []  80.49 59.24 0 top
NOREF#61  -  []  37.43 84.33 90 top
NOREF#62  -  []  72.97 29.23 0 top
NOREF#63  -  []  58.86 97.48 0 top
NOREF#64  -  []  130.81 18.41 89.9 top
NOREF#65  -  []  200.03 99.06 0 top
NOREF#66  -  []  -103.1 337.85 0 top
NOREF#67  -  []  46.48 127 0 top
NOREF#68  -  []  185.12 49.05 0 top
NOREF#69  -  []  96.52 17.14 90 top
NOREF#70  -  []  66.21 55.31 0 top
NOREF#71  -  []  41.55 40.72 0 top
NOREF#72  -  []  0 80.52 0 top
NOREF#73  -  []  59.78 85.82 90 top
NOREF#74  -  []  200.03 0 90 top
NOREF#75  -  []  72.97 15 0 top
NOREF#76  -  []  30.8 88.04 0 top
NOREF#77  -  []  24.78 61.6 0 top
NOREF#78  -  []  51.19 98.58 0 top
NOREF#79  -  []  12.7 210.06 0 top
NOREF#80  -  []  399.11 149.63 0 top
NOREF#81  -  []  72.97 29.23 0 top
NOREF#82  -  []  130.81 18.41 0 top
NOREF#83  -  []  0 63.04 0 top
NOREF#84  -  []  17.02 109.98 90 top
NOREF#85  -  []  21.59 206.5 90 top
NOREF#86  -  []  70.24 86.84 0 top
NOREF#87  -  []  41.28 59.69 0 top
NOREF#88  -  []  69.73 86.55 0 top
NOREF#89  -  []  191.29 46.84 0 top
NOREF#90  -  []  17.02 17.02 0 top
NOREF#91  -  []  41.86 33.22 0 top
NOREF#92  -  []  72.03 95.13 0 top
NOREF#93  -  []  131.52 70.38 0 top
NOREF#94  -  []  24.85 74.36 0 top
NOREF#95  -  []  59.91 101.41 0 top
NOREF#96  -  []  53.24 34.39 0 top
NOREF#97  -  []  41.28 33.02 90 top
NOREF#98  -  []  71.92 33.15 0 top
NOREF#99  -  []  12.7 207.9 90 top
NOREF#100  -  []  105.26 69.36 0 top
NOREF#101  -  []  49.66 16.51 90 top
NOREF#102  -  []  118.92 23.8 180 bottom
PP1  PROBE POINT  [PROBE_POINT_22PAD]  177.65 36.22 270 top
PP2  PROBE POINT  [PROBE_POINT_22PAD]  82.68 5.87 90 top
PP3  PROBE POINT  [PROBE_POINT_22PAD]  79.76 14.5 90 top
PP4  PROBE POINT  [PROBE_POINT_22PAD]  134.26 12.73 90 top
PP5  PROBE POINT  [PROBE_POINT_22PAD]  146.48 22.63 0 top
PP6  PROBE POINT  [PROBE_POINT_22PAD]  143.48 10.85 90 top
PP7  PROBE POINT  [PROBE_POINT_22PAD]  107.62 22.61 0 top
PP8  PROBE POINT  [PROBE_POINT_22PAD]  116.59 16.87 0 top
PP9  PROBE POINT  [PROBE_POINT_22PAD]  105.08 7.42 0 top
PP10  PROBE POINT  [PROBE_POINT_22PAD]  93.55 32.08 270 top
PP11  PROBE POINT  [PROBE_POINT_22PAD]  105.18 12.24 0 top
PP12  PROBE POINT  [PROBE_POINT_22PAD]  98.12 31.95 270 top
PP13  PROBE POINT  [PROBE_POINT_22PAD]  105.18 16.87 0 top
PP14  PROBE POINT  [PROBE_POINT_22PAD]  80.77 32.05 270 top
PP15  PROBE POINT  [PROBE_POINT_22PAD]  95.35 23.72 0 top
PP16  PROBE POINT  [PROBE_POINT_22PAD]  89.71 21.62 270 top
PP17  PROBE POINT  [PROBE_POINT_22PAD]  85.12 32.05 270 top
PP18  PROBE POINT  [PROBE_POINT_22PAD]  105.84 31.39 0 top
PP19  PROBE POINT  [PROBE_POINT_22PAD]  89.38 32.05 270 top
PP20  PROBE POINT  [PROBE_POINT_22PAD]  113.18 34.14 270 top
PP21  PROBE POINT  [PROBE_POINT_22PAD]  119.23 29.95 0 top
PP22  PROBE POINT  [PROBE_POINT_22PAD]  122.1 18.01 270 top
PP23  PROBE POINT  [PROBE_POINT_22PAD]  128.12 14.07 0 top
PP24  PROBE POINT  [PROBE_POINT_22PAD]  131.65 36.02 270 top
PP25  PROBE POINT  [PROBE_POINT_22PAD]  147.88 33.76 0 top
PP26  PROBE POINT  [PROBE_POINT_22PAD]  139.65 36.04 270 top
PP27  PROBE POINT  [PROBE_POINT_22PAD]  122.91 34.67 270 top
PP28  PROBE POINT  [PROBE_POINT_22PAD]  130.1 30.02 0 top
PP29  PROBE POINT  [PROBE_POINT_22PAD]  212.73 45.08 0 top
PP30  PROBE POINT  [PROBE_POINT_22PAD]  211.46 43.81 0 top
PP31  PROBE POINT  [PROBE_POINT_22PAD]  211.46 48.89 0 top
PP32  PROBE POINT  [PROBE_POINT_22PAD]  166.57 36.5 0 top
Q1  DTC114EET1G  [SOT_416_3_63X31]  119.15 97.18 180 bottom
Q2  DTC114EET1G  [SOT_416_3_63X31]  121.56 97.18 180 bottom
Q3  DTC114EET1G  [SOT_416_3_63X31]  125.6 94.36 180 bottom
Q4  DTC114EET1G  [SOT_416_3_63X31]  128.14 94.36 180 bottom
Q5  DTC114EET1G  [SOT_416_3_63X31]  130.56 94.36 180 bottom
Q6  DTC114EET1G  [SOT_416_3_63X31]  133.1 94.36 180 bottom
Q7  DTC114EET1G  [SOT_416_3_63X31]  135.76 94.36 180 bottom
Q8  DTC114EET1G  [SOT_416_3_63X31]  138.18 94.36 180 bottom
Q9  DTC114EET1G  [SOT_416_3_63X31]  140.72 94.36 180 bottom
Q10  DTC114EET1G  [SOT_416_3_63X31]  143.26 94.36 180 bottom
Q11  DTC114EET1G  [SOT_416_3_63X31]  145.92 94.36 180 bottom
Q12  DTC114EET1G  [SOT_416_3_63X31]  148.46 94.36 180 bottom
Q13  DTC114EET1G  [SOT_416_3_63X31]  151 94.36 180 bottom
Q14  DTC114EET1G  [SOT_416_3_63X31]  153.54 94.36 180 bottom
Q15  DTC114EET1G  [SOT_416_3_63X31]  156.08 94.36 180 bottom
Q16  DTC114EET1G  [SOT_416_3_63X31]  158.62 94.36 180 bottom
Q17  DTC114EET1G  [SOT_416_3_63X31]  161.04 94.36 180 bottom
Q18  DTC114EET1G  [SOT_416_3_63X31]  163.58 94.36 180 bottom
Q19  DTC114EET1G  [SOT_416_3_63X31]  166.24 94.36 180 bottom
Q20  DTC114EET1G  [SOT_416_3_63X31]  168.78 94.36 180 bottom
Q21  DTC114EET1G  [SOT_416_3_63X31]  200.03 31.57 90 top
Q22  DTC114EET1G  [SOT_416_3_63X31]  194.87 31.65 90 top
Q23  DTC114EET1G  [SOT_416_3_63X31]  190.17 31.67 90 top
Q24  CSD18532Q5  [SON_Q5B_8]  186.36 11.84 270 bottom
Q25  SiA517DJ  [SC70-6L_85X85]  91.11 18.06 90 top
Q26  DTC114EET1G  [SOT_416_3_63X31]  158.27 5.08 180 top
Q27  DTC114EET1G  [SOT_416_3_63X31]  158.14 8.43 270 top
R1  0  [0402]  27.06 64.03 0 bottom
R2  49.9  [0402]  31.53 64.67 90 bottom
R3  0  [0402]  36.63 61.06 270 bottom
R4  0  [0402]  21.64 62.89 0 bottom
R5  100  [0201]  53.57 63.5 270 bottom
R6  49.9  [0201]  36.37 68.91 90 bottom
R7  49.9  [0402]  20.27 62.37 270 bottom
R8  0  [0402]  27.13 62.62 0 bottom
R9  49.9  [0402]  31.6 62.24 270 bottom
R10  0  [0402]  36.63 63.6 90 bottom
R11  0  [0402]  44.09 61.44 270 bottom
R12  0  [0201]  43 62.08 0 bottom
R13  0  [0201]  43 62.71 0 bottom
R14  0  [0402]  44.09 63.35 90 bottom
R15  100  [0201]  100.89 81.69 180 bottom
R16  100  [0201]  99.62 81.69 0 bottom
R17  1K  [0402]  119.41 117.5 270 bottom
R18  604  [0402]  117.88 96.04 90 top
R19  604  [0402]  120.29 96.04 90 top
R20  1K  [0201]  61.95 62.71 45 bottom
R21  0  [0201]  67.59 52.76 0 top
R22  1K  [0402]  135.23 122.83 270 bottom
R23  1K  [0402]  142.6 122.76 270 bottom
R24  1K  [0402]  149.63 122.89 270 bottom
R25  1K  [0402]  156.84 122.89 270 bottom
R26  604  [0402]  123.06 93.73 0 bottom
R27  1K  [0402]  113.56 122.86 270 bottom
R28  1K  [0402]  120.68 122.86 270 bottom
R29  1K  [0402]  128.02 122.68 270 bottom
R30  1k  [0402]  156.44 87.55 180 bottom
R31  3.65k  [0201]  51.16 69.9 270 bottom
R32  0  [0402]  153.54 113.16 270 bottom
R33  0  [0402]  151.05 113.13 270 bottom
R34  0  [0402]  158.72 113.18 270 bottom
R35  0  [0402]  156.11 113.16 270 bottom
R36  0  [0402]  161.42 113.18 270 bottom
R37  0  [0402]  163.7 113.18 270 bottom
R38  0  [0402]  168.78 113.18 270 bottom
R39  0  [0402]  166.24 113.18 270 bottom
R40  0  [0402]  151.97 113.13 90 bottom
R41  0  [0402]  154.46 113.16 90 bottom
R42  0  [0402]  157.02 113.16 90 bottom
R43  0  [0402]  159.64 113.18 90 bottom
R44  0  [0402]  162.33 113.18 90 bottom
R45  0  [0402]  164.62 113.18 90 bottom
R46  0  [0402]  167.16 113.18 90 bottom
R47  0  [0402]  169.7 113.18 90 bottom
R48  0 ohm  [0201]  45.95 46.54 255 top
R50  0  [0402]  39.31 21.03 165 top
R52  0  [0402]  40.04 23.71 165 top
R54  0  [0402]  39.19 22.49 75 top
R58  0 ohm  [0201]  46.59 46.37 255 top
R72  0  [0402]  65.25 19.4 195 top
R73  0 ohm  [0201]  58.21 44.82 285 top
R74  0  [0402]  64.52 22.05 195 top
R76  0  [0402]  64.39 20.59 105 top
R77  0 ohm  [0201]  58.85 44.99 285 top
R93  0  [0402]  41.45 103.79 195 top
R94  0  [0402]  40.6 104.99 285 top
R95  0 ohm  [0201]  46.12 80.57 105 top
R96  0  [0402]  40.74 106.44 195 top
R97  0 ohm  [0201]  46.75 80.74 105 top
R114  0 ohm  [0201]  58.6 82.13 75 top
R115  0  [0402]  66.02 106.04 255 top
R116  0 ohm  [0201]  59.23 81.96 75 top
R118  0  [0402]  66.87 107.23 165 top
R119  0  [0402]  66.16 104.59 165 top
R136  0  [0402]  26.56 43.05 30 top
R137  100  [01005]  46.84 57.1 90 top
R138  0  [0402]  27.52 44.19 120 top
R139  0  [0402]  25.1 42.79 120 top
R140  0  [0402]  22.12 58.27 0 top
R141  100  [01005]  46.81 60.27 90 top
R142  0  [0402]  23.51 58.78 90 top
R143  0  [0402]  20.72 58.78 90 top
R144  0  [0402]  27.7 86.25 330 top
R145  100  [01005]  47.45 71.07 45 top
R146  0  [0402]  29.15 86.02 60 top
R147  0  [0402]  26.77 87.38 60 top
R148  0  [0402]  22.17 71.01 0 top
R149  100  [01005]  46.81 66.67 90 top
R150  0  [0402]  23.57 71.52 90 top
R151  0  [0402]  20.78 71.52 90 top
R152  24.9K  [0201]  107.72 112.29 45 top
R153  39k  [0201]  98.15 92.89 0 top
R154  240  [0201]  105.74 83.52 180 bottom
R155  240  [0201]  107.01 83.52 0 bottom
R156  0  [0201]  104.8 83.19 270 bottom
R157  49.9  [0201]  98.65 100.28 180 bottom
R158  0  [0201]  104.19 83.19 270 bottom
R159  0  [0603]  97.89 104.39 270 bottom
R160  620  [0201]  107.98 95.53 90 top
R161  18  [0402]  97.96 109.39 270 bottom
R162  240  [0201]  103.86 84.12 180 bottom
R163  240  [0201]  105.13 84.12 0 bottom
R164  292  [0402]  97.45 110.76 180 bottom
R165  292  [0402]  97.42 107.99 180 bottom
R166  49.9  [0402]  99.26 101.04 0 bottom
R167  120  [0201]  98.17 83.29 315 bottom
R168  120  [0201]  97.25 84.21 135 bottom
R169  100  [0201]  100.56 82.63 270 bottom
R170  49.9  [0201]  95.05 105.16 270 bottom
R171  49.9  [0201]  95.05 103.89 90 bottom
R172  100  [0201]  99.95 82.63 270 bottom
R173  200  [0201]  100.89 83.57 0 bottom
R174  200  [0201]  99.62 83.57 180 bottom
R175  130  [0201]  102.87 100.23 0 bottom
R176  240  [0201]  109.42 93.8 90 bottom
R177  240  [0201]  109.42 92.53 270 bottom
R178  100  [0201]  103.2 102.44 270 bottom
R179  82  [0201]  102.87 103.38 180 bottom
R180  49.9  [0201]  102.87 99.62 180 bottom
R181  130  [0201]  104.14 100.23 180 bottom
R182  240  [0201]  110.03 94.41 270 bottom
R183  240  [0201]  110.03 95.68 90 bottom
R184  100  [0201]  103.81 102.44 270 bottom
R185  82  [0201]  104.14 103.38 0 bottom
R186  49.9  [0201]  104.14 99.62 0 bottom
R187  240  [0201]  94.23 89.84 270 bottom
R188  240  [0201]  94.23 91.11 90 bottom
R189  0  [0201]  110.31 88.19 0 bottom
R190  240  [0201]  109.37 88.52 90 bottom
R191  0  [0201]  110.31 87.58 0 bottom
R192  240  [0201]  109.37 87.25 270 bottom
R193  240  [0201]  94.84 87.96 270 bottom
R194  240  [0201]  94.84 89.23 90 bottom
R195  1.3K  [0201]  104.09 86.89 270 top
R196  0  [0402]  102.74 83.46 90 bottom
R197  750  [0402]  113.51 88.32 180 bottom
R198  750  [0402]  113.54 86.39 180 bottom
R199  750  [0402]  113.54 82.58 180 bottom
R200  750  [0402]  113.54 84.48 180 bottom
R201  604  [0402]  201.19 33.73 180 top
R202  0  [0402]  200.69 30.68 180 top
R203  604  [0402]  196.04 33.81 180 top
R204  0  [0402]  195.53 30.73 180 top
R205  0  [0402]  202.18 64.54 180 top
R206  0  [0402]  190.83 30.76 180 top
R207  604  [0402]  191.34 33.83 180 top
R208  0  [0402]  190.45 91.13 90 top
R209  3.01K  [0402]  195.96 103.61 0 bottom
R210  0  [0402]  194.74 115.72 90 top
R211  10  [0402]  193.83 115.72 270 top
R212  10  [0402]  192.91 115.72 270 top
R213  4.7K  [0402]  188.37 109.58 180 bottom
R214  12K  [0402]  189.15 106.07 270 bottom
R215  1K  [0402]  188.37 110.49 0 bottom
R216  10K  [0402]  186.59 110.49 0 bottom
R217  10K  [0402]  189.05 99.59 0 bottom
R218  10K  [0402]  187.83 98.04 270 bottom
R219  10K  [0402]  186.51 98.09 270 bottom
R220  2.2K  [0402]  186.51 99.87 270 bottom
R221  1k  [0402]  179.15 15.34 270 top
R222  0  [0402]  177.65 28.14 270 bottom
R223  0  [0402]  176.73 28.14 270 bottom
R224  0  [0402]  175.82 29.34 270 bottom
R228  12.7k  [0402]  93.62 6.65 0 top
R229  0  [0402]  81.41 14 90 bottom
R232  25.5k  [0402]  80.39 14 270 bottom
R233  10k  [0402]  91.72 6.65 0 top
R234  0  [0402]  153.95 6.76 180 bottom
R235  5.1  [0402]  153.6 13.3 0 top
R236  1  [0402]  150.67 13.87 0 top
R237  1k  [0402]  155.7 15.93 0 top
R238  0  [0402]  143.48 11.38 90 bottom
R239  20.5k  [0402]  155.7 16.84 0 top
R240  49.9  [0402]  154.33 18.16 270 top
R241  25.5k  [0402]  144.4 12.37 90 bottom
R243  30.1k  [0402]  157.48 16.84 0 top
R244  1.78k  [0402]  153.85 8.33 90 bottom
R245  7.87k  [0402]  157.48 15.93 180 top
R246  0  [0402]  167.11 11.63 270 bottom
R247  324k  [0402]  162.68 12.78 0 top
R248  120k  [0402]  162.71 13.73 0 top
R249  0  [0402]  117.04 15.65 0 top
R250  25.5k  [0402]  117.04 14.73 180 top
R251  0  [0402]  119.46 11.86 90 bottom
R252  0  [0402]  114.12 8.92 90 bottom
R253  0  [0402]  115.27 8.84 270 bottom
R254  0  [0402]  116.21 8.84 270 bottom
R255  0  [0402]  88.6 21.11 270 top
R256  25.5k  [0402]  87.68 21.11 90 top
R257  0  [0402]  84.53 18.67 0 bottom
R258  0  [0402]  81.48 22.91 180 bottom
R259  0  [0402]  81.48 22 180 bottom
R260  0  [0402]  80.82 19.51 90 bottom
R261  0  [0402]  121.74 24.74 90 bottom
R262  0  [0402]  119.59 28.68 0 top
R263  0  [0402]  117.2 22.38 180 bottom
R264  25.5k  [0402]  119.59 27.74 180 top
R265  0  [0402]  117.32 21.21 0 bottom
R266  0  [0402]  119.79 20.57 90 bottom
R267  0  [0402]  130.76 8.81 90 bottom
R268  0  [0402]  128.47 12.75 0 top
R269  25.5k  [0402]  128.47 11.81 180 top
R270  0  [0402]  126.67 5.77 270 bottom
R271  0  [0402]  127.58 5.77 270 bottom
R272  0  [0402]  128.93 5.18 0 bottom
R273  0  [0402]  150.65 28.93 90 bottom
R274  0  [0402]  148.22 32.69 0 top
R275  25.5k  [0402]  148.22 31.77 180 top
R276  0  [0402]  146.08 25.43 0 bottom
R277  0  [0402]  146.08 26.47 180 bottom
R278  0  [0402]  147.42 25.86 270 bottom
R279  0  [0402]  135.25 24.54 0 top
R280  0  [0402]  130.61 28.65 0 top
R281  25.5k  [0402]  130.61 27.74 180 top
R282  0  [0402]  128.52 21.14 0 bottom
R283  0  [0402]  129.87 21.74 270 bottom
R284  0  [0402]  131.03 20.5 90 bottom
R285  0  [0402]  131.95 20.5 90 bottom
R286  4.99K  [0402]  212.12 91.74 180 top
R287  604  [0402]  211.46 88.8 90 top
R288  0  [0402]  206.02 87.35 135 top
R289  240  [0201]  94.84 92.99 90 bottom
R290  240  [0201]  94.84 91.72 270 bottom
R291  240  [0201]  95.5 94.87 90 bottom
R292  240  [0201]  95.5 93.6 270 bottom
R293  240  [0201]  110.03 90.65 270 bottom
R294  240  [0201]  110.03 91.92 90 bottom
R295  100  [0201]  50.17 63.47 270 bottom
R296  100  [0201]  54.36 63.5 270 bottom
R297  0  [0402]  163.83 28.42 90 bottom
R298  0  [0402]  165.74 28.42 270 bottom
R299  0  [0402]  164.8 28.42 270 bottom
R300  0  [0402]  163.8 30.28 270 bottom
R301  49.9  [0402]  155.27 18.21 270 top
R302  49.9  [0201]  81.25 46.94 180 bottom
R303  49.9  [0201]  83.11 38.81 180 bottom
R304  49.9  [0201]  77.34 76.96 180 bottom
R305  49.9  [0201]  77.34 76.2 180 bottom
R306  1M  [0402]  90.17 18.21 90 bottom
R307  1M  [0402]  89.18 12.34 270 top
R308  100k  [0402]  81.92 25.65 0 top
R309  49.9  [0201]  83.11 37.13 180 bottom
R310  49.9  [0201]  83.13 40.49 180 bottom
R311  49.9  [0201]  77.34 77.72 180 bottom
R312  49.9  [0201]  77.34 80.01 180 bottom
R313  49.9  [0201]  77.37 83.36 180 bottom
R314  49.9  [0201]  77.34 81.81 180 bottom
R315  49.9  [0201]  83.11 42.11 180 bottom
R316  49.9  [0201]  80.24 48.26 180 bottom
R317  49.9  [0201]  83.13 43.92 180 bottom
R318  49.9  [0201]  83.13 45.44 180 bottom
R319  49.9  [0201]  77.34 79.22 180 bottom
R320  49.9  [0201]  77.34 82.58 180 bottom
R321  0  [0402]  156.69 18.21 90 top
R322  49.9  [0201]  38.18 62.03 180 bottom
R323  49.9  [0201]  38.18 62.74 180 bottom
R324  100k  [0402]  112.42 9.27 270 top
R325  100k  [0402]  114.76 22.38 270 top
R326  100k  [0402]  143.69 26.31 270 top
R327  100k  [0402]  123.8 6.17 90 top
R328  1k  [0402]  158.5 8.43 0 bottom
R329  1K  [0402]  159.55 5.01 180 top
R330  0  [0402]  44.84 19.55 165 top
R331  0  [0402]  45.56 22.23 165 top
R332  0  [0402]  44.71 21.01 75 top
R333  0 ohm  [0201]  51.47 45.06 255 top
R334  0 ohm  [0201]  52.11 44.89 255 top
R335  0  [0402]  70.75 20.88 195 top
R336  0  [0402]  70.04 23.53 195 top
R337  0  [0402]  69.91 22.07 105 top
R338  0 ohm  [0201]  63.73 46.3 285 top
R339  0 ohm  [0201]  64.37 46.47 285 top
R340  0  [0402]  46.26 107.92 195 top
R341  0  [0402]  46.97 105.27 195 top
R342  0  [0402]  46.12 106.47 285 top
R343  0 ohm  [0201]  51.64 82.05 105 top
R344  0 ohm  [0201]  52.27 82.22 105 top
R345  0  [0402]  72.39 105.76 165 top
R346  0  [0402]  71.68 103.11 165 top
R347  0  [0402]  71.54 104.56 255 top
R348  0 ohm  [0201]  64.12 80.66 75 top
R349  0 ohm  [0201]  64.75 80.48 75 top
RS1  0.05  [0805]  82.04 11.07 0 top
RS2  0.001  [2512]  144.3 18.01 0 bottom
RS3  0.05  [0805]  115.21 16.21 270 top
RS4  0.05  [0805]  89.15 22.94 180 top
RS5  0.05  [0805]  117.78 29.36 270 top
RS6  0.05  [0805]  126.67 13.26 270 top
RS7  0.05  [0805]  146.41 33.27 270 top
RS8  0.05  [0805]  128.83 29.29 270 top
SHIELD1  -  [4T4R_TX_SHIELD]  27.34 47.38 30 top
SHIELD2  -  [4T4R_TX_SHIELD]  24.78 61.6 0 top
SHIELD3  -  [4T4R_TX_SHIELD]  24.85 74.36 0 top
SHIELD4  -  [4T4R_TX_SHIELD]  31.79 87.77 330 top
SHIELD5  -  [4T4R_RX_SHIELD]  50.87 25.56 165 top
SHIELD6  -  [4T4R_RX_SHIELD]  72.97 29.23 195 top
SHIELD7  -  [4T4R_RX_SHIELD]  37.56 97.95 15 top
SHIELD8  -  [4T4R_RX_SHIELD]  59.91 101.41 345 top
SJP1  SOLDER JUMPER, 0402  [SMD_JUMPER_L_0402]  110.18 110.47 135 top
SW1  AFE RESET  [SW_THVT_SPST_PTS635SL43]  118.39 116.99 0 top
T1  TCM2-43X+  [TFMR_6_160X150_50]  41.38 70.43 180 bottom
T2  NCR2-113+  [BALUN_6_NCR2]  24.33 63.26 270 bottom
